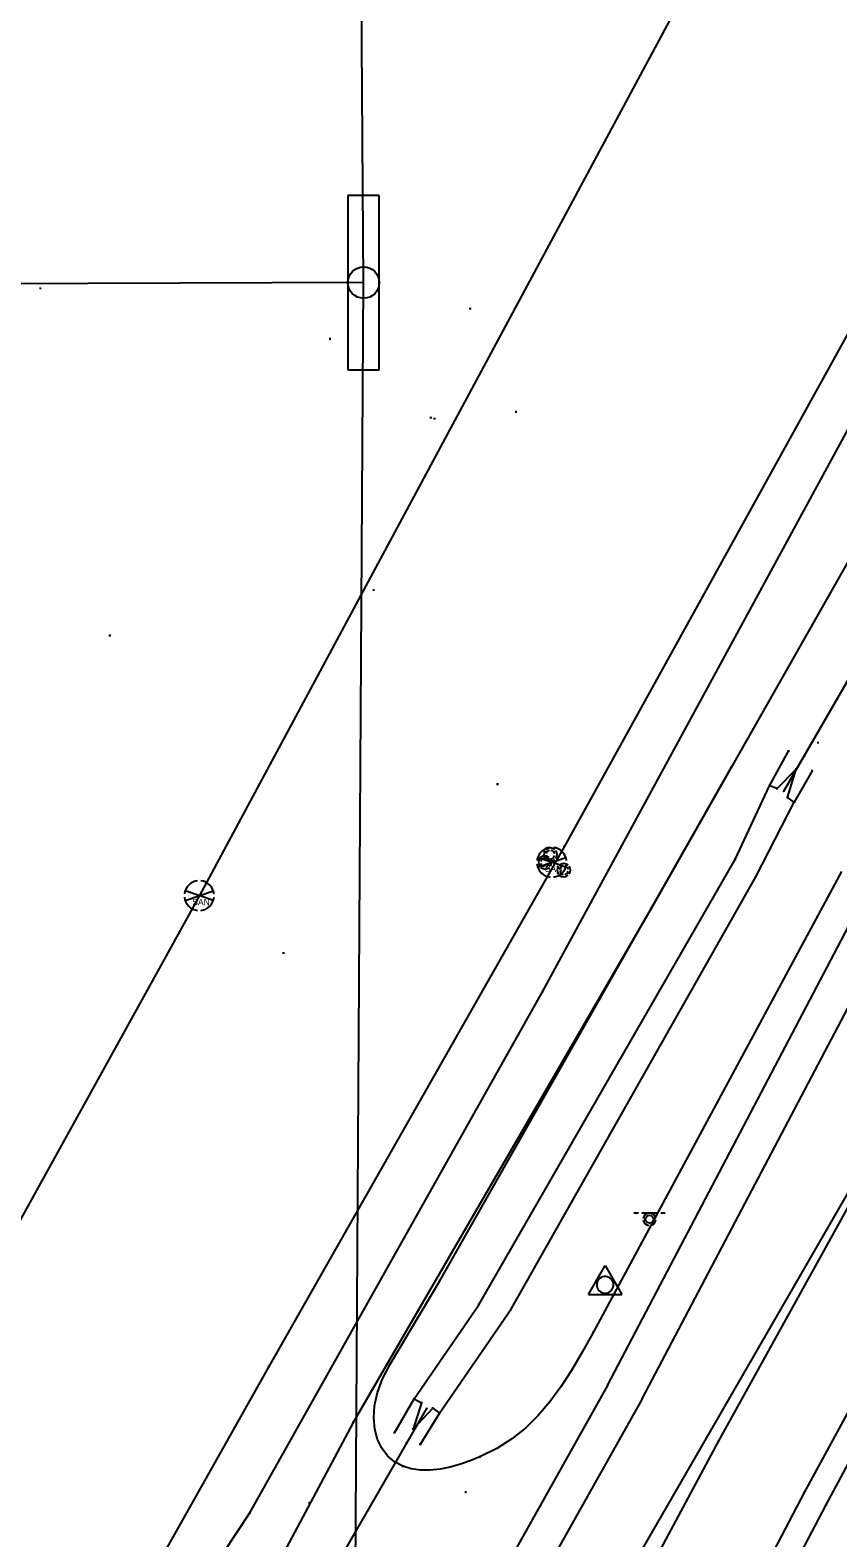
# Model space of a CAD drawing. Extents: x 1954856 to 2011933, y 399149 to 426294.
# Drawn here: x 2006495.1 to 2006616.9, y 402218.3 to 402445.5 of the extents above; entities that cross this region are included whole.
import ezdxf

# ---------------------------------------------------------------- set-up
doc = ezdxf.new("R2010")
doc.units = 0
for name, color, linetype in [('BankMent_ep', 7, 'Continuous'), ('BaselineSurvey', 7, 'Continuous'), ('Bollard_ep', 7, 'Continuous'), ('EndTreatMES_ep', 7, 'Continuous'), ('FlowLineInvert_ep', 7, 'Continuous'), ('GovQtrSectCnrEW_ep', 7, 'Continuous'), ('GovQuarterLine_ep', 7, 'Continuous'), ('GovTwpRgeLine_ep', 7, 'Continuous'), ('GroundShot_ep', 7, 'Continuous'), ('MonumentIRC_ep', 7, 'Continuous'), ('PavtAsphalt_ep', 7, 'Continuous'), ('PavtAsphaltCrown_ep', 7, 'Continuous'), ('PipeCulvert_ep', 7, 'Continuous'), ('PointLocator_ep', 7, 'Continuous'), ('SanitaryFM_B_ep', 7, 'Continuous'), ('ShldrPaved_ep', 7, 'Continuous'), ('SignSingle_ep', 7, 'Continuous'), ('ValveCvrSewer_ep', 7, 'Continuous'), ('WaterA_ep', 7, 'Continuous'), ('WaterNP_B_ep', 7, 'Continuous')]:
    doc.layers.add(name, color=color, linetype=linetype)

msp = doc.modelspace()

# ---------------------------------------------------------------- linework, layer by layer
at = {"layer": 'BankMent_ep'}
for p, q in [((2006556.85, 402257.06), (2006600.83, 402334.42)), ((2006617.44, 402318.69), (2006579.98, 402249.25)), ((2006549.37, 402244.47), (2006556.85, 402257.06))]:
    msp.add_line(p, q, dxfattribs=at)
for points in [[(2006553.01, 402239.27), (2006562.73, 402253.45), (2006601.42, 402320.53), (2006606.57, 402331.63)], [(2006556.82, 402237.12), (2006567.67, 402252.89), (2006604.52, 402317.9), (2006610.31, 402329.13)], [(2006579.98, 402249.25), (2006578.35, 402246.28), (2006576.74, 402243.55), (2006575.13, 402241.06), (2006573.46, 402238.79), (2006571.71, 402236.74), (2006569.82, 402234.89), (2006567.75, 402233.25), (2006565.46, 402231.79), (2006562.9, 402230.52), (2006561.47, 402229.93), (2006559.97, 402229.42), (2006558.45, 402228.99), (2006556.92, 402228.69), (2006555.41, 402228.52), (2006553.96, 402228.52), (2006552.57, 402228.71), (2006551.29, 402229.1), (2006550.06, 402229.77), (2006549, 402230.68), (2006548.13, 402231.81), (2006547.48, 402233.15), (2006547.06, 402234.68), (2006546.9, 402236.38), (2006547.03, 402238.22), (2006547.47, 402240.2), (2006548.24, 402242.28), (2006549.37, 402244.47)]]:
    msp.add_lwpolyline(points, dxfattribs=at)
at = {"layer": 'BaselineSurvey'}
msp.add_lwpolyline([(2006095.1, 401364.22), (2006751.44, 402500.64), (2007687.69, 404121.69)], dxfattribs=at)
at = {"layer": 'Bollard_ep'}
for p, q in [((2006572.73, 402320.08), (2006572.73, 402320.08)), ((2006573.54, 402321.25), (2006573.54, 402321.25)), ((2006575.58, 402318.89), (2006575.58, 402318.89))]:
    msp.add_line(p, q, dxfattribs=at)
for centre, radius, start, end in [((2006573.54, 402321.25), 1, 144.0654, 216.3889), ((2006573.54, 402321.25), 1, 49.5137, 130.9405), ((2006573.54, 402321.25), 0.65, 100.1266, 169.8734), ((2006573.54, 402321.25), 0.65, 10.1266, 79.8734), ((2006573.54, 402321.25), 1, 324.0654, 36.3889), ((2006572.73, 402320.08), 1, 144.0654, 216.3889), ((2006572.73, 402320.08), 1, 49.5137, 130.9405), ((2006572.73, 402320.08), 1, 229.5137, 310.9405), ((2006572.73, 402320.08), 0.65, 100.1266, 169.8734), ((2006572.73, 402320.08), 0.65, 190.1266, 259.8734), ((2006572.73, 402320.08), 0.65, 10.1266, 79.8734), ((2006572.73, 402320.08), 0.65, 280.1266, 349.8734), ((2006573.54, 402321.25), 1, 229.5137, 310.9405), ((2006573.54, 402321.25), 0.65, 190.1266, 259.8734), ((2006572.73, 402320.08), 1, 324.0654, 36.3889), ((2006573.54, 402321.25), 0.65, 280.1266, 349.8734), ((2006575.58, 402318.89), 1, 144.0654, 216.3889), ((2006575.58, 402318.89), 1, 49.5137, 130.9405), ((2006575.58, 402318.89), 0.65, 100.1266, 169.8734), ((2006575.58, 402318.89), 0.65, 10.1266, 79.8734), ((2006575.58, 402318.89), 1, 324.0654, 36.3889), ((2006575.58, 402318.89), 1, 229.5137, 310.9405), ((2006575.58, 402318.89), 0.65, 190.1266, 259.8734), ((2006575.58, 402318.89), 0.65, 280.1266, 349.8734)]:
    msp.add_arc(centre, radius, start, end, dxfattribs=at)
at = {"layer": 'EndTreatMES_ep'}
for p, q in [((2006606.57, 402331.63), (2006609.46, 402336.84)), ((2006610.6, 402334.12), (2006607.71, 402331.19)), ((2006609.31, 402329.88), (2006610.6, 402334.12)), ((2006613, 402333.87), (2006610.31, 402329.13)), ((2006607.71, 402331.19), (2006606.57, 402331.63)), ((2006610.31, 402329.13), (2006609.31, 402329.88)), ((2006550.04, 402234.16), (2006553.01, 402239.27)), ((2006554.12, 402238.64), (2006552.85, 402234.71)), ((2006552.85, 402234.71), (2006555.81, 402237.87)), ((2006553.01, 402239.27), (2006554.12, 402238.64)), ((2006555.81, 402237.87), (2006556.82, 402237.12)), ((2006556.82, 402237.12), (2006553.93, 402232.41))]:
    msp.add_line(p, q, dxfattribs=at)
at = {"layer": 'FlowLineInvert_ep'}
for p, q in [((2006608.81, 402330.7), (2006608.63, 402330.88)), ((2006608.81, 402330.88), (2006608.63, 402330.7)), ((2006608.72, 402330.79), (2006608.72, 402330.79)), ((2006554.99, 402237.71), (2006554.82, 402237.88)), ((2006554.99, 402237.88), (2006554.82, 402237.71)), ((2006554.91, 402237.8), (2006554.91, 402237.8))]:
    msp.add_line(p, q, dxfattribs=at)
at = {"layer": 'GovQtrSectCnrEW_ep'}
for p, q in [((2006547.74, 402420.55), (2006543.02, 402420.55)), ((2006543.02, 402420.55), (2006543.02, 402394.3)), ((2006547.74, 402394.3), (2006547.74, 402420.55)), ((2006545.38, 402407.42), (2006545.38, 402407.42)), ((2006543.02, 402394.3), (2006547.74, 402394.3))]:
    msp.add_line(p, q, dxfattribs=at)
msp.add_circle((2006545.38, 402407.42), 2.36, dxfattribs=at)
at = {"layer": 'GovQuarterLine_ep'}
msp.add_line((2006545.38, 402407.42), (2003871.74, 402398.78), dxfattribs=at)
at = {"layer": 'GovTwpRgeLine_ep'}
for p, q in [((2006545.38, 402407.42), (2006525, 405025.34)), ((2006528.85, 399746.53), (2006545.38, 402407.42))]:
    msp.add_line(p, q, dxfattribs=at)
at = {"layer": 'GroundShot_ep'}
for p, q in [((2006496.77, 402406.55), (2006496.52, 402406.55)), ((2006496.65, 402406.43), (2006496.65, 402406.68)), ((2006496.65, 402406.55), (2006496.65, 402406.55)), ((2006561.59, 402403.48), (2006561.34, 402403.48)), ((2006561.46, 402403.36), (2006561.46, 402403.61)), ((2006561.46, 402403.48), (2006561.46, 402403.48)), ((2006540.45, 402398.93), (2006540.2, 402398.93)), ((2006540.32, 402398.8), (2006540.32, 402399.05)), ((2006540.32, 402398.93), (2006540.32, 402398.93)), ((2006568.48, 402387.95), (2006568.23, 402387.95)), ((2006568.36, 402387.83), (2006568.36, 402388.08)), ((2006568.36, 402387.95), (2006568.36, 402387.95)), ((2006556.2, 402386.92), (2006555.95, 402386.92)), ((2006556.07, 402386.79), (2006556.07, 402387.04)), ((2006556.07, 402386.92), (2006556.07, 402386.92)), ((2006547.04, 402361.11), (2006546.79, 402361.11)), ((2006546.92, 402360.98), (2006546.92, 402361.23)), ((2006546.92, 402361.11), (2006546.92, 402361.11)), ((2006507.27, 402354.25), (2006507.02, 402354.25)), ((2006507.14, 402354.13), (2006507.14, 402354.38)), ((2006507.14, 402354.25), (2006507.14, 402354.25)), ((2006565.7, 402331.84), (2006565.45, 402331.84)), ((2006565.57, 402331.72), (2006565.57, 402331.97)), ((2006565.57, 402331.84), (2006565.57, 402331.84)), ((2006533.44, 402306.41), (2006533.19, 402306.41)), ((2006533.32, 402306.29), (2006533.32, 402306.54)), ((2006533.32, 402306.41), (2006533.32, 402306.41))]:
    msp.add_line(p, q, dxfattribs=at)
at = {"layer": 'MonumentIRC_ep'}
for p, q in [((2006579.29, 402255), (2006581.79, 402259.33)), ((2006581.79, 402259.33), (2006584.29, 402255)), ((2006581.79, 402256.44), (2006581.79, 402256.44)), ((2006579.29, 402255), (2006584.29, 402255))]:
    msp.add_line(p, q, dxfattribs=at)
msp.add_arc((2006581.79, 402256.44), 1.26, 209.9294, 209.03, dxfattribs=at)
at = {"layer": 'PavtAsphalt_ep'}
for p, q in [((2006611.84, 402225.17), (2006658.62, 402311.19)), ((2006587.38, 402239.25), (2006537.92, 402151.41)), ((2006565.67, 402136.68), (2006611.84, 402225.17))]:
    msp.add_line(p, q, dxfattribs=at)
msp.add_lwpolyline([(2006587.38, 402239.25), (2006632.9, 402325.68), (2006676.6, 402406.68), (2006719.3, 402486.76), (2006766.12, 402572.65), (2006813.14, 402654.7), (2006869.81, 402752.59), (2006897.05, 402800.14)], dxfattribs=at)
at = {"layer": 'PavtAsphaltCrown_ep'}
msp.add_lwpolyline([(2006556.31, 402153.47), (2006598.88, 402232.86), (2006646.06, 402318.03), (2006692.96, 402398.13), (2006739.04, 402476.05), (2006774.51, 402537.27), (2006833.25, 402640.67), (2006890.64, 402739.98), (2006917.74, 402787.19)], dxfattribs=at)
at = {"layer": 'PipeCulvert_ep'}
for points in [[(2006608.72, 402330.79), (2006656.38, 402413.09)], [(2006507.42, 402155.58), (2006554.91, 402237.8)]]:
    msp.add_lwpolyline(points, dxfattribs=at)
at = {"layer": 'PointLocator_ep'}
for p, q in [((2006555.66, 402387.05), (2006555.41, 402387.05)), ((2006555.54, 402386.93), (2006555.54, 402387.18)), ((2006555.54, 402387.05), (2006555.54, 402387.05)), ((2006614.02, 402338.11), (2006613.77, 402338.11)), ((2006613.9, 402337.99), (2006613.9, 402338.24)), ((2006613.9, 402338.11), (2006613.9, 402338.11)), ((2006609.59, 402336.84), (2006609.34, 402336.84)), ((2006609.46, 402336.72), (2006609.46, 402336.97)), ((2006609.46, 402336.84), (2006609.46, 402336.84)), ((2006612, 402336.18), (2006611.75, 402336.18)), ((2006611.88, 402336.05), (2006611.88, 402336.3)), ((2006611.88, 402336.18), (2006611.88, 402336.18)), ((2006600.96, 402334.42), (2006600.71, 402334.42)), ((2006600.83, 402334.3), (2006600.83, 402334.55)), ((2006600.83, 402334.42), (2006600.83, 402334.42)), ((2006610.72, 402334.12), (2006610.47, 402334.12)), ((2006610.6, 402334), (2006610.6, 402334.25)), ((2006610.6, 402334.12), (2006610.6, 402334.12)), ((2006613.13, 402333.87), (2006612.88, 402333.87)), ((2006613, 402333.75), (2006613, 402334)), ((2006613, 402333.87), (2006613, 402333.87)), ((2006606.7, 402331.63), (2006606.45, 402331.63)), ((2006606.7, 402331.63), (2006606.45, 402331.63)), ((2006606.57, 402331.5), (2006606.57, 402331.75)), ((2006606.57, 402331.5), (2006606.57, 402331.75)), ((2006606.57, 402331.63), (2006606.57, 402331.63)), ((2006606.57, 402331.63), (2006606.57, 402331.63)), ((2006607.83, 402331.19), (2006607.58, 402331.19)), ((2006607.71, 402331.07), (2006607.71, 402331.32)), ((2006607.71, 402331.19), (2006607.71, 402331.19)), ((2006609.43, 402329.88), (2006609.18, 402329.88)), ((2006609.31, 402329.76), (2006609.31, 402330.01)), ((2006609.31, 402329.88), (2006609.31, 402329.88)), ((2006610.44, 402329.13), (2006610.19, 402329.13)), ((2006610.44, 402329.13), (2006610.19, 402329.13)), ((2006610.31, 402329.01), (2006610.31, 402329.26)), ((2006610.31, 402329.01), (2006610.31, 402329.26)), ((2006610.31, 402329.13), (2006610.31, 402329.13)), ((2006610.31, 402329.13), (2006610.31, 402329.13)), ((2006575.74, 402322.42), (2006575.49, 402322.42)), ((2006575.62, 402322.29), (2006575.62, 402322.54)), ((2006575.62, 402322.42), (2006575.62, 402322.42)), ((2006601.55, 402320.53), (2006601.3, 402320.53)), ((2006601.42, 402320.41), (2006601.42, 402320.66)), ((2006601.42, 402320.53), (2006601.42, 402320.53)), ((2006604.64, 402317.9), (2006604.39, 402317.9)), ((2006604.52, 402317.77), (2006604.52, 402318.02)), ((2006604.52, 402317.9), (2006604.52, 402317.9)), ((2006520.77, 402315.09), (2006520.52, 402315.09)), ((2006520.64, 402314.97), (2006520.64, 402315.22)), ((2006520.64, 402315.09), (2006520.64, 402315.09)), ((2006588.85, 402313.14), (2006588.6, 402313.14)), ((2006588.72, 402313.01), (2006588.72, 402313.26)), ((2006588.72, 402313.14), (2006588.72, 402313.14)), ((2006572.48, 402300.58), (2006572.23, 402300.58)), ((2006572.35, 402300.46), (2006572.35, 402300.71)), ((2006572.35, 402300.58), (2006572.35, 402300.58)), ((2006556.97, 402257.06), (2006556.72, 402257.06)), ((2006556.85, 402256.94), (2006556.85, 402257.19)), ((2006556.85, 402257.06), (2006556.85, 402257.06)), ((2006562.85, 402253.45), (2006562.6, 402253.45)), ((2006562.73, 402253.33), (2006562.73, 402253.58)), ((2006562.73, 402253.45), (2006562.73, 402253.45)), ((2006567.79, 402252.89), (2006567.54, 402252.89)), ((2006567.67, 402252.77), (2006567.67, 402253.02)), ((2006567.67, 402252.89), (2006567.67, 402252.89)), ((2006580.11, 402249.25), (2006579.86, 402249.25)), ((2006579.98, 402249.12), (2006579.98, 402249.37)), ((2006579.98, 402249.25), (2006579.98, 402249.25)), ((2006549.49, 402244.47), (2006549.24, 402244.47)), ((2006549.37, 402244.34), (2006549.37, 402244.59)), ((2006549.37, 402244.47), (2006549.37, 402244.47)), ((2006531.22, 402244.15), (2006530.97, 402244.15)), ((2006531.09, 402244.03), (2006531.09, 402244.28)), ((2006531.09, 402244.15), (2006531.09, 402244.15)), ((2006582.32, 402241.38), (2006582.07, 402241.38)), ((2006582.19, 402241.25), (2006582.19, 402241.5)), ((2006582.19, 402241.38), (2006582.19, 402241.38)), ((2006553.14, 402239.27), (2006552.89, 402239.27)), ((2006553.14, 402239.27), (2006552.89, 402239.27)), ((2006553.01, 402239.14), (2006553.01, 402239.39)), ((2006553.01, 402239.14), (2006553.01, 402239.39)), ((2006553.01, 402239.27), (2006553.01, 402239.27)), ((2006553.01, 402239.27), (2006553.01, 402239.27)), ((2006554.25, 402238.64), (2006554, 402238.64)), ((2006554.12, 402238.52), (2006554.12, 402238.77)), ((2006554.12, 402238.64), (2006554.12, 402238.64)), ((2006555.94, 402237.87), (2006555.69, 402237.87)), ((2006555.81, 402237.75), (2006555.81, 402238)), ((2006555.81, 402237.87), (2006555.81, 402237.87)), ((2006587.5, 402239.25), (2006587.25, 402239.25)), ((2006587.38, 402239.12), (2006587.38, 402239.38)), ((2006587.38, 402239.25), (2006587.38, 402239.25)), ((2006543.96, 402235.68), (2006543.71, 402235.68)), ((2006543.83, 402235.56), (2006543.83, 402235.81)), ((2006543.83, 402235.68), (2006543.83, 402235.68)), ((2006556.95, 402237.12), (2006556.7, 402237.12)), ((2006556.95, 402237.12), (2006556.7, 402237.12)), ((2006556.82, 402236.99), (2006556.82, 402237.24)), ((2006556.82, 402236.99), (2006556.82, 402237.24)), ((2006556.82, 402237.12), (2006556.82, 402237.12)), ((2006556.82, 402237.12), (2006556.82, 402237.12)), ((2006550.16, 402234.16), (2006549.91, 402234.16)), ((2006550.04, 402234.03), (2006550.04, 402234.28)), ((2006550.04, 402234.16), (2006550.04, 402234.16)), ((2006552.98, 402234.71), (2006552.73, 402234.71)), ((2006552.85, 402234.59), (2006552.85, 402234.84)), ((2006552.85, 402234.71), (2006552.85, 402234.71)), ((2006551.96, 402232.6), (2006551.71, 402232.6)), ((2006551.83, 402232.48), (2006551.83, 402232.73)), ((2006551.83, 402232.6), (2006551.83, 402232.6)), ((2006554.06, 402232.41), (2006553.81, 402232.41)), ((2006553.93, 402232.29), (2006553.93, 402232.54)), ((2006553.93, 402232.41), (2006553.93, 402232.41)), ((2006599.01, 402232.86), (2006598.76, 402232.86)), ((2006598.88, 402232.73), (2006598.88, 402232.98)), ((2006598.88, 402232.86), (2006598.88, 402232.86)), ((2006551.41, 402229.1), (2006551.16, 402229.1)), ((2006551.29, 402228.98), (2006551.29, 402229.23)), ((2006551.29, 402229.1), (2006551.29, 402229.1)), ((2006563.03, 402230.52), (2006562.78, 402230.52)), ((2006562.9, 402230.4), (2006562.9, 402230.65)), ((2006562.9, 402230.52), (2006562.9, 402230.52)), ((2006560.91, 402225.19), (2006560.66, 402225.19)), ((2006560.79, 402225.07), (2006560.79, 402225.32)), ((2006560.79, 402225.19), (2006560.79, 402225.19)), ((2006611.96, 402225.17), (2006611.71, 402225.17)), ((2006611.84, 402225.05), (2006611.84, 402225.3)), ((2006611.84, 402225.17), (2006611.84, 402225.17)), ((2006528.37, 402222.08), (2006528.12, 402222.08)), ((2006528.24, 402221.95), (2006528.24, 402222.2)), ((2006528.24, 402222.08), (2006528.24, 402222.08)), ((2006537.35, 402223.59), (2006537.1, 402223.59)), ((2006537.23, 402223.47), (2006537.23, 402223.72)), ((2006537.23, 402223.59), (2006537.23, 402223.59)), ((2006615.26, 402223.31), (2006615.01, 402223.31)), ((2006615.14, 402223.18), (2006615.14, 402223.43)), ((2006615.14, 402223.31), (2006615.14, 402223.31))]:
    msp.add_line(p, q, dxfattribs=at)
at = {"layer": 'SanitaryFM_B_ep'}
for points in [[(2007401.95, 403818.63), (2007312.3, 403645.73), (2007290.75, 403604.1), (2007263.4, 403556.68), (2007243.69, 403523.41), (2007211.46, 403477.24), (2007146.71, 403360.43), (2007074.94, 403233.14), (2007057.11, 403197.22), (2007018.41, 403142.13), (2006986.05, 403110.09), (2006967.4, 403089.86), (2006949.18, 403062), (2006912.39, 403001.77), (2006860.92, 402920.48), (2006691.88, 402620.5), (2006600.9, 402464.44), (2006520.64, 402315.09), (2006403, 402102.49), (2006392.62, 402085.16), (2006366.88, 402033.22), (2006268.08, 401998.8), (2006240.51, 401985.14), (2006227.32, 401976.32)], [(2007078.74, 403198.4), (2007031.79, 403125.31), (2006978.01, 403035.87), (2006927.36, 402959.7), (2006863.76, 402845.21), (2006819, 402760.68), (2006799.33, 402721.33), (2006714.07, 402569.46), (2006673.75, 402500.47), (2006641.55, 402441.62), (2006575.62, 402322.42), (2006531.09, 402244.15), (2006469.22, 402134.35), (2006427.42, 402069.13), (2006371.5, 401989.4)]]:
    msp.add_lwpolyline(points, dxfattribs=at)
at = {"layer": 'ShldrPaved_ep'}
for p, q in [((2006615.14, 402223.31), (2006661.27, 402309.63)), ((2006582.19, 402241.38), (2006533.31, 402154.13)), ((2006568.57, 402135.19), (2006615.14, 402223.31))]:
    msp.add_line(p, q, dxfattribs=at)
msp.add_lwpolyline([(2006582.19, 402241.38), (2006625.25, 402323.34), (2006628.8, 402328.64), (2006667.07, 402400.6), (2006715.18, 402489.37), (2006762.2, 402574.85), (2006809.77, 402657.38), (2006865.61, 402754.45), (2006893.49, 402802.15)], dxfattribs=at)
at = {"layer": 'SignSingle_ep'}
for p, q in [((2006586.12, 402267.27), (2006586.82, 402267.27)), ((2006587.32, 402267.27), (2006589.67, 402267.27)), ((2006590.17, 402267.27), (2006590.87, 402267.27)), ((2006588.49, 402266.32), (2006588.49, 402266.32))]:
    msp.add_line(p, q, dxfattribs=at)
msp.add_circle((2006588.49, 402266.32), 0.594, dxfattribs=at)
for start, end in [(96.0423, 173.9577), (6.0423, 83.9577), (186.0423, 263.9577), (276.0423, 353.9577)]:
    msp.add_arc((2006588.49, 402266.32), 0.95, start, end, dxfattribs=at)
at = {"layer": 'ValveCvrSewer_ep'}
for p, q in [((2006571.62, 402319.38), (2006575.89, 402320.8)), ((2006575.89, 402319.38), (2006571.62, 402320.8)), ((2006573.75, 402320.09), (2006573.75, 402320.09)), ((2006518.46, 402314.36), (2006522.73, 402315.78)), ((2006522.73, 402314.36), (2006518.46, 402315.78)), ((2006520.6, 402315.07), (2006520.6, 402315.07))]:
    msp.add_line(p, q, dxfattribs=at)
for centre, start, end in [((2006573.75, 402320.09), 96.3794, 173.6206), ((2006573.75, 402320.09), 6.3794, 83.6206), ((2006573.75, 402320.09), 186.3794, 263.6206), ((2006573.75, 402320.09), 276.3794, 353.6206), ((2006520.6, 402315.07), 96.3794, 173.6206), ((2006520.6, 402315.07), 6.3794, 83.6206), ((2006520.6, 402315.07), 186.3794, 263.6206), ((2006520.6, 402315.07), 276.3794, 353.6206)]:
    msp.add_arc(centre, 2.25, start, end, dxfattribs=at)
at = {"layer": 'WaterA_ep'}
msp.add_lwpolyline([(2007183.71, 403343.35), (2007159.89, 403302.21), (2007091.06, 403185.8), (2007048.72, 403112.53), (2006998.4, 403024.32), (2006953.5, 402944.34), (2006900.79, 402854.48), (2006848.29, 402761.17), (2006824.2, 402718.39), (2006722.16, 402548.68), (2006655.5, 402430.73), (2006588.72, 402313.14), (2006543.83, 402235.68), (2006485.84, 402127.23), (2006385.47, 401948.84)], dxfattribs=at)
at = {"layer": 'WaterNP_B_ep'}
msp.add_lwpolyline([(2006433.99, 402042.9), (2006456.16, 402086.4), (2006478.36, 402126.14), (2006495.22, 402164.8), (2006504.71, 402186.55), (2006528.24, 402222.08), (2006572.35, 402300.58), (2006631.69, 402409.75), (2006664.85, 402468.85), (2006775.08, 402656.4), (2006826.97, 402745.97), (2006874.88, 402831.28), (2006921.38, 402912.75), (2006944.33, 402952.47), (2006965.19, 402991.67), (2007050.42, 403136.24), (2007082.62, 403193.93), (2007116.1, 403252.38), (2007160.14, 403327.81), (2007179.84, 403361.08), (2007198.99, 403394.85)], dxfattribs=at)

# ---------------------------------------------------------------- texts
at = {"layer": 'ValveCvrSewer_ep'}
for p in [(2006572.71, 402318.65), (2006519.56, 402313.63)]:
    msp.add_text('SAN', height=0.95, dxfattribs=at).set_placement(p)

doc.saveas('drawing.dxf')
